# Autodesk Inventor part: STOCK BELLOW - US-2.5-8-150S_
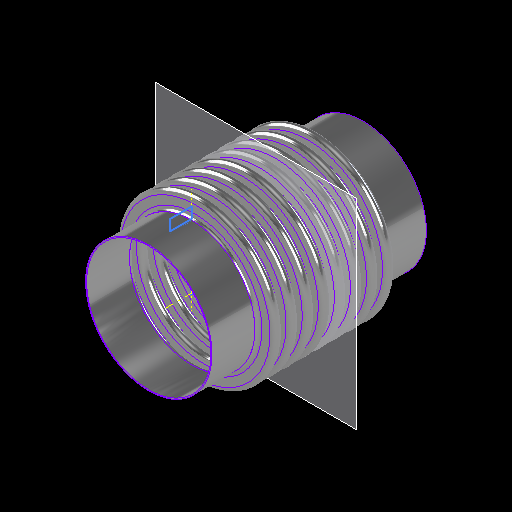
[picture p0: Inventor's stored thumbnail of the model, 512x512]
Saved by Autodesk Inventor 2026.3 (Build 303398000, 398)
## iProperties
RuleStatus: InUse
Created: 2026-07
Part Number: STOCK BELLOW - US-2.5-8-150S_
Material: STARTING WITH
Document SubType Name: Modeling
Designer: GS
Appearance: NEW
Mass: 38.7367 g
Surface Area: 1279.42 cm^2
Volume: 38.7367 cm^3
Density: 1 g/cm^3
Author: GS
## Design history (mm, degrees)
derived "STOCK BELLOW - US-2.5-8-150S.ipt"
  sketch "ID BELLOW MOUNT CALC"
    geometry: L1 (44.45, 0)-(38.1, 0); L2 (38.1, 0)-(38.1, 12.7); L3 (38.1, 12.7)-(44.45, 12.7); L4 (44.45, 12.7)-(44.45, 0); L5 (36.513, 12.7)-(35.598, 12.7); L6 (35.598, 12.7)-(35.598, 0); L7 (35.598, 0)-(36.513, 0); L8 (36.513, 0)-(36.513, 12.7); L9 (0, -2.54)-(0, 15.24); L10 (-8.89, 0)-(53.34, 0); 1 further point
    constraints: 20 end point
  node "STOCK BELLOW MIDPLANE"
node "SBELLOW_"
feature "SBELLOW_::STOCK BELLOW - US-2.5-8-150S.ipt" dims "d5" = 10
feature "STANGENT_::STOCK BELLOW - US-2.5-8-150S.ipt" dims "d5" = 10
feature "SSAME_TAN::STOCK BELLOW - US-2.5-8-150S.ipt" dims "d5" = 10
tag "TaggingFeature2"
sketch "Sketch12"
  geometry: 1 further point
node "STANGENT_"
node "SSAME_TAN"
